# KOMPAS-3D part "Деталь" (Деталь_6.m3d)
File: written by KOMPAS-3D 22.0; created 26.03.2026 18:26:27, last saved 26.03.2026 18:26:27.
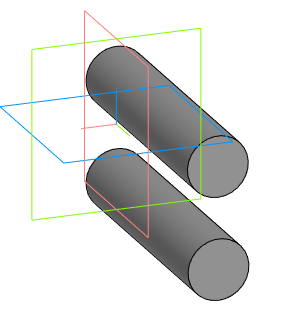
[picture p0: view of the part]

Document properties: Автор: Пользователь Windows; Полное имя файла: F:\Танк\Деталь_6.m3d

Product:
- Part/product: Деталь

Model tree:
1. Операция без истории:1
2. Операция без истории:2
